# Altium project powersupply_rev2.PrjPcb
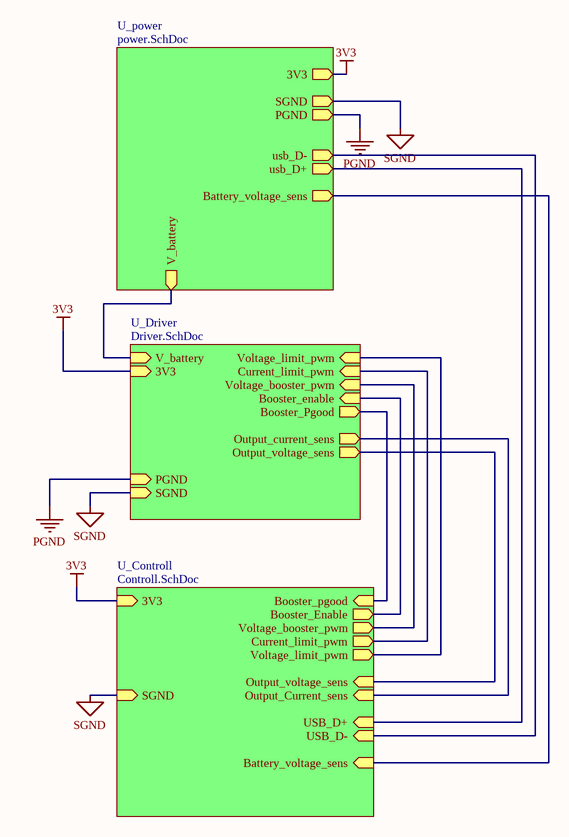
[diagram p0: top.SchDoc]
16 sheets, 127 parts. Net scope: strictly hierarchical (ports join the sheet entries above them; power ports are local).
Board file: PCB1.PcbDoc
Sheets:
  top.SchDoc
    U_power = power.SchDoc
      LDO = LDO.SchDoc
      Battery = battery.SchDoc
      U_usb = usb.SchDoc
      U_usb_isolator = usb_isolator.SchDoc
    U_Driver = Driver.SchDoc
      U_Booster = Booster.SchDoc
      pta_I = pwm_to_analog.SchDoc
      U_current_sense = current_sense.SchDoc
      U_linear_regulator = linear_regulator.SchDoc
      pta_I = pwm_to_analog.SchDoc
      pta_I = pwm_to_analog.SchDoc
    U_Controll = Controll.SchDoc
      U_knobs = knobs.SchDoc
      U_mcu = mcu.SchDoc
      U_Display = Display.SchDoc
      U_programmer = programmer.SchDoc

## Sheet top.SchDoc
size A3

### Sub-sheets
U_Controll = Controll.SchDoc: 3V3 (in), SGND (in), Booster_pgood (in), Booster_Enable (out), Voltage_limit_pwm (out), Current_limit_pwm (out), USB_D+ (in), USB_D- (in), Battery_voltage_sens (in), Voltage_booster_pwm (out), Output_voltage_sens (in), Output_Current_sens (in)
U_Driver = Driver.SchDoc: V_battery (in), SGND (in), PGND (in), 3V3 (in), Voltage_limit_pwm (in), Current_limit_pwm (in), Booster_enable (in), Booster_Pgood (out), Voltage_booster_pwm (in), Output_current_sens (out), Output_voltage_sens (out)
U_power = power.SchDoc: usb_D- (out), usb_D+ (out), 3V3 (out), SGND (out), PGND (out), V_battery (out), Battery_voltage_sens (out)

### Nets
3V3: sheet U_power/3V3, sheet U_Driver/3V3, sheet U_Controll/3V3
PGND: sheet U_power/PGND, sheet U_Driver/PGND
SGND: sheet U_power/SGND, sheet U_Driver/SGND, sheet U_Controll/SGND  [project net GND]
Net*2_3: sheet U_Driver/Output_current_sens, sheet U_Controll/Output_Current_sens
NetC17_1: sheet U_power/V_battery, sheet U_power/Battery_voltage_sens, sheet U_Driver/V_battery, sheet U_Controll/Battery_voltage_sens
NetIC1_1: sheet U_Driver/Booster_enable, sheet U_Controll/Booster_Enable
NetIC1_17: sheet U_Driver/Booster_Pgood, sheet U_Controll/Booster_pgood
NetR20_pta_I1_1: sheet U_Driver/Current_limit_pwm, sheet U_Controll/Current_limit_pwm
NetR20_pta_I2_1: sheet U_Driver/Voltage_limit_pwm, sheet U_Controll/Voltage_limit_pwm
NetR20_pta_I3_1: sheet U_Driver/Voltage_booster_pwm, sheet U_Controll/Voltage_booster_pwm
NetR24_2: sheet U_power/usb_D+, sheet U_Controll/USB_D+
NetR26_2: sheet U_power/usb_D-, sheet U_Controll/USB_D-
NetR29_1: sheet U_Driver/Output_voltage_sens, sheet U_Controll/Output_voltage_sens

## Sheet power.SchDoc
size A3
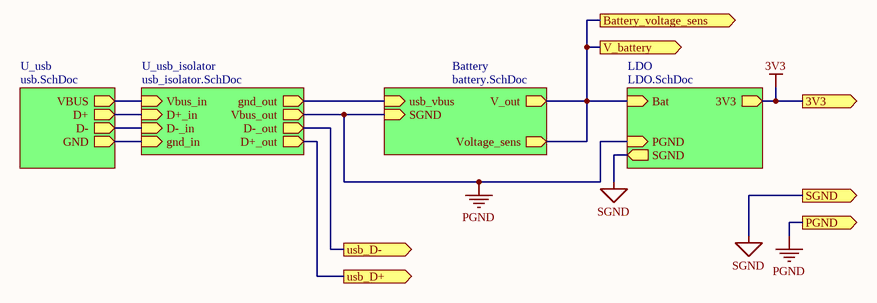
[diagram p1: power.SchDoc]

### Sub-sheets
Battery = battery.SchDoc: V_out (out), Voltage_sens (out), usb_vbus (in), SGND (in)
LDO = LDO.SchDoc: Bat (in), PGND (in), 3V3 (out), SGND (out)
U_usb = usb.SchDoc: VBUS (out), GND (out), D+ (out), D- (out)
U_usb_isolator = usb_isolator.SchDoc: Vbus_in (in), D+_in (in), D-_in (in), gnd_in (in), gnd_out (out), D-_out (out), D+_out (out), Vbus_out (out)

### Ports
3V3 (out), Battery_voltage_sens (out), PGND (out), SGND (out), usb_D+ (out), usb_D- (out), V_battery (out)

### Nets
3V3: port 3V3, sheet LDO/3V3
PGND: port PGND, sheet LDO/PGND, sheet Battery/SGND, sheet U_usb_isolator/Vbus_out
SGND: port SGND, sheet LDO/SGND  [project net GND]
NetC13_2: sheet Battery/usb_vbus, sheet U_usb_isolator/gnd_out
NetC17_1: port V_battery, port Battery_voltage_sens, sheet LDO/Bat, sheet Battery/V_out, sheet Battery/Voltage_sens
NetC42_1: sheet U_usb/GND, sheet U_usb_isolator/gnd_in
NetC42_2: sheet U_usb/VBUS, sheet U_usb_isolator/Vbus_in
NetJ1_A6: sheet U_usb/D+, sheet U_usb_isolator/D+_in
NetJ1_A7: sheet U_usb/D-, sheet U_usb_isolator/D-_in
NetR24_2: port usb_D+, sheet U_usb_isolator/D+_out
NetR26_2: port usb_D-, sheet U_usb_isolator/D-_out

## Sheet LDO.SchDoc
size A4
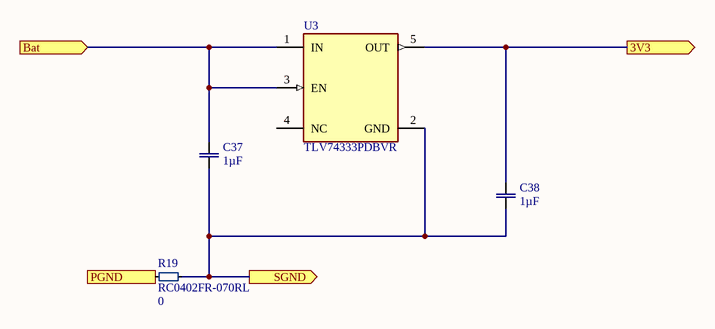
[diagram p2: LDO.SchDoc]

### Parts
C37  Capacitance: 1µF  [CAP0805]  (hidden comment: CL21B105KBFNNNG)
C38  Capacitance: 1µF  [CAP0805]  (hidden comment: CL21B105KBFNNNG)
R19  RC0402FR-070RL  Resistance: 0  [SMD_0402(1005)_M]
U3  TLV74333PDBVR  [FP-DBV0005A-IPC_A]

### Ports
3V3 (out), Bat (in), PGND (in), SGND (out)

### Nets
3V3: C38.2 U3.5(OUT) ; port 3V3
GND: C37.1 C38.1 R19.2 U3.2(GND) ; port SGND
PGND: R19.1 ; port PGND
NetC17_1: C37.2 U3.1(IN) U3.3(EN) ; port Bat

Not connected (* = marked no-connect by the designer): U3 4(NC)

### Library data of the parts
C37 C38 = CMP-0001-00012-4: SAMSUNG ELECTRO-MECHANICS - CL21B105KBFNNNG - MLCC CAPACITORS; Voltage Rating: 50V; Dielectric: X7R; Material: Ceramic; Tolerance: 10%
R19 = CMP-0001-00005-6: Res Thick Film 0402 0 Ohm Molded SMD SMD Paper T/R; Value: 0; Temperature Coefficient: 200ppm/°C; Power Rating: 62.5mW; Voltage Rating: 50V; Tolerance: 1%
U3 = CMP-00004-1: 300mA Low-Dropout (LDO) Regulator 5-SOT-23 -40 to 125; Power Supply Rejection Ratio (PSRR): 28dB; Dropout Voltage: 270mV; Min Output Voltage: 3.3V; Output Configuration: Positive; Max Input Voltage: 5.5V; Output Type: Fixed; Number of Regulators: 1; Quiescent Current: 60uA

## Sheet battery.SchDoc
size A4
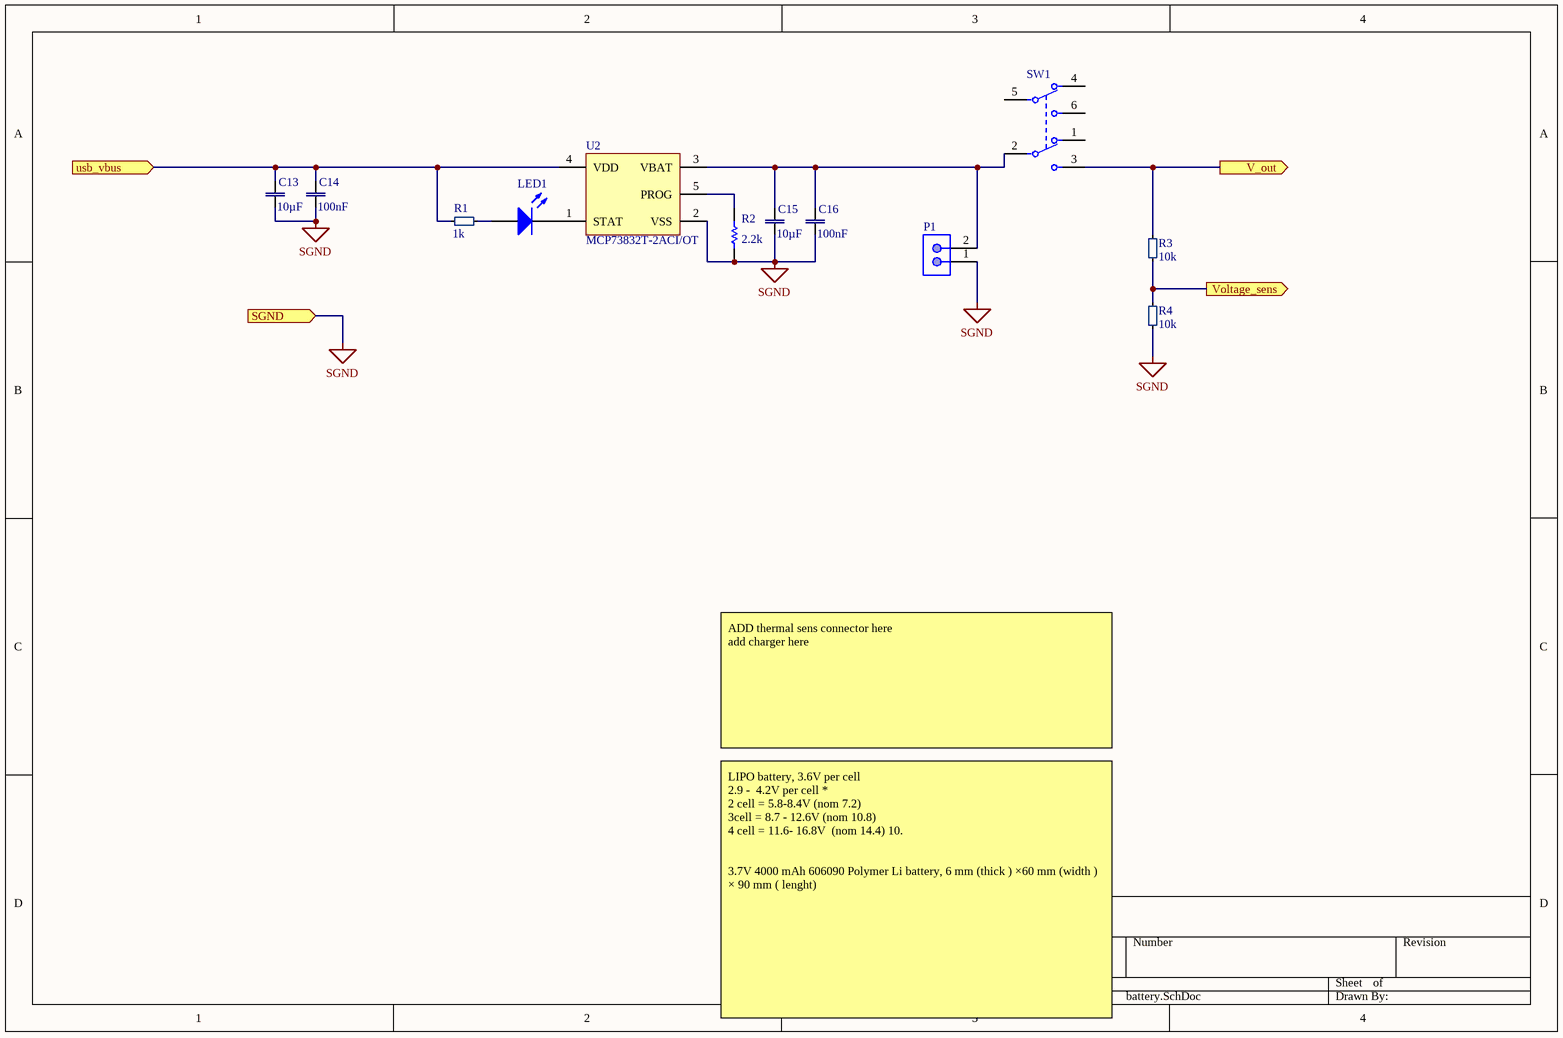
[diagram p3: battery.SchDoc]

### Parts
C13  Capacitance: 10µF  [Chip2PinSM127P600-8N]  (hidden comment: CL31A106MBHNNNE)
C14  Capacitance: 100nF  [cap0402]  (hidden comment: GRM155R71H104ME14D)
C15  Capacitance: 10µF  [Chip2PinSM127P600-8N]  (hidden comment: CL31A106MBHNNNE)
C16  Capacitance: 100nF  [cap0402]  (hidden comment: GRM155R71H104ME14D)
LED1  150080BS75000  [0805_A]  (value not drawn)
P1  B2B-XH-A(LF)(SN)  [JST-B2B-XH-A_V]  (value not drawn)
R1  Resistance: 1k  [SMD_0402(1005)_M]  (hidden comment: RC0402FR-071KL)
R2  Resistance: 2.2k  [RESC1005X40X25NL05T10]  (hidden comment: RC0402FR-072K2L)
R3  Resistance: 10k  [SMD_0402(1005)_M]  (hidden comment: RC0402FR-0710KL)
R4  Resistance: 10k  [SMD_0402(1005)_M]  (hidden comment: RC0402FR-0710KL)
SW1  100DP1T2B3M2QEH  [FP-100DP1T2B3M2QEH-MFG]  (value not drawn)
U2  MCP73832T-2ACI/OT  [SOT-23-OT5_M]

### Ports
SGND (in), usb_vbus (in), V_out (out), Voltage_sens (out)

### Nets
SGND: C13.1 C14.1 C15.1 C16.1 P1.1 R2.1 R4.1 U2.2(VSS) ; port SGND  [project net PGND]
NetC13_2: C13.2 C14.2 R1.2 U2.4(VDD) ; port usb_vbus
NetC15_2: C15.2 C16.2 P1.2 SW1.2 U2.3(VBAT)
NetC17_1: R3.1 R3.2 R4.2 SW1.3 ; port V_out, port Voltage_sens
NetLED1_1: LED1.1(K) U2.1(STAT)
NetLED1_2: LED1.2(A) R1.1
NetR2_2: R2.2 U2.5(PROG)

Not connected (* = marked no-connect by the designer): SW1 1 4 5 6

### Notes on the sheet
- ADD thermal sens connector here
  add charger here
- LIPO battery, 3.6V per cell
  2.9 -  4.2V per cell *
  2 cell = 5.8-8.4V (nom 7.2)
  3cell = 8.7 - 12.6V (nom 10.8)
  4 cell = 11.6- 16.8V  (nom 14.4) 10.
  3.7V 4000 mAh 606090 Polymer Li battery, 6 mm (thick ) ×60 mm (width ) × 90 mm ( lenght)

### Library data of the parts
C13 C15 = CMP-0001-00015-2: CAP CER 10UF 50V X5R 1206; Capacitor Type: Ceramic; Tolerance: 20%
C14 C16 = CMP-0001-00001-8: 0402 0.1 uF 50 V ±20% Tolerance X7R SMT Monolithic Ceramic Chip Capacitor; Value: 100nF; Voltage Rating: 50V
LED1 = CMP-00002-1: SMD LED blue 3.5 V 0805, 150080BS75000, Würth Elektronik; Dominant Wavelength: 470nm; Luminous Intensity: 145mcd; Lens Style: Clear,Rectangular; Forward Current: 30mA; Test Current: 20mA; Forward Voltage: 3.2V; Viewing Angle: 140°
P1 = CMP-ROOT-00008-1: Conn Shrouded Header (4 Sides) HDR 2 POS 2.5mm Solder ST Thru-Hole Box; Max Current Rating: 3A; Connector Type: Male Pin; Contact Resistance: 20mR; Max Voltage Rating (DC): 250V; System: Connector; Wire/Cable Gauge: 22AWG; Number of Contacts: 2; Insulation Resistance: 1GR
R1 = CMP-001-0000-7: Surface Mount Chip Resistor, Thick Film, RC Series, 1 kohm, 62.5 mW, 1%, 50 V, 0402 [1005 Metric]; Temperature Coefficient: 100ppm/°C; Value: 1k; Voltage Rating: 50V; Power Rating: 62.5mW
R2 = CMP-001-0020-3: RES SMD 2.2K OHM 1% 1/16W 0402; Temperature Coefficient: 100ppm/°C; Voltage Rating: 50V; Power Rating: 63mW
R3 R4 = CMP-008-0005-9: Surface Mount Thick Film Resistor, Rc Series, 10 Kohm, 62.5 Mw, - 1%, 50 V, 0402 [1005 Metric]; Voltage Rating (DC): 50V; Value: 10k; Temperature Coefficient: 100ppm/°C; Power Rating: 62.5mW
SW1 = CMP-ROOT-00014-1: 100 Series DPDT On-None-On Through Hole Miniature Toggle Switch; Illumination Type: Non-Illuminated; Actuator Type: Standard Round; Switch Function: On-On; Actuator Length: 6.86mm; Voltage Rating (AC): 120V; Actuator Material: Brass,Chrome; Current Rating: 5A; Voltage Rating (DC): 28V; Electrical Life: 40000Cycles
U2 = CMP-006-0003-2: BATTERY CHARGER, 500mA, SOT23-5; Battery Type:Li-Ion, Li-Pol; Input Voltage:6V; Battery Charge Voltage:4.2V; Charge Current Max:500mA; Battery IC Case Style:SOT-23; No. of Pins:5; No. of Series Cells:1; Operating Temperature Max:85 C; Max Supply Voltage: 6V; Number of Cells: 1; Max Output Voltage: 4.5V; Max Power Dissipation: 1.54W; Min Supply Voltage: 3.75V; Min Output Voltage: 4.168V; Output Current: 10mA; Output Voltage: 4.2V

## Sheet usb.SchDoc
size A3
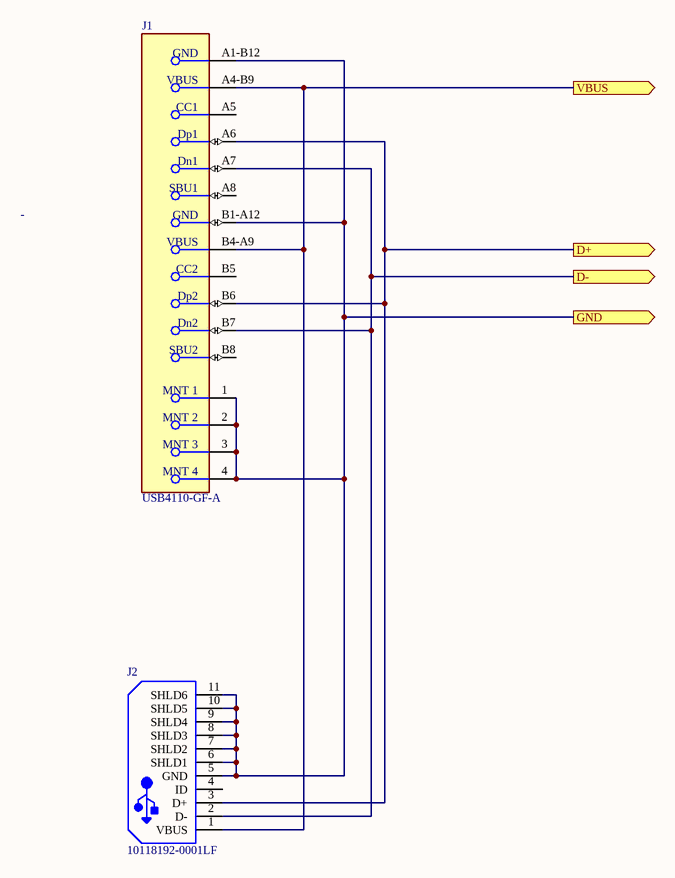
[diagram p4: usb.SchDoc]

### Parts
J1  USB4110-GF-A  [FP-USB4110-GF-A-MFG]
J2  10118192-0001LF  [FCI-10118192-0001LF-5_V]

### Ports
D+ (out), D- (out), GND (out), VBUS (out)

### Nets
NetC42_1: J1.1(MNT_1) J1.2(MNT_2) J1.3(MNT_3) J1.4(MNT_4) J1.A1-B12(GND) J1.B1-A12(GND) J2.5(GND) J2.6(SHLD1) J2.7(SHLD2) J2.8(SHLD3) J2.9(SHLD4) J2.10(SHLD5) J2.11(SHLD6) ; port GND
NetC42_2: J1.A4-B9(VBUS) J1.B4-A9(VBUS) J2.1(VBUS) ; port VBUS
NetJ1_A6: J1.A6(Dp1) J1.B6(Dp2) J2.3(D+) ; port D+
NetJ1_A7: J1.A7(Dn1) J1.B7(Dn2) J2.2(D-) ; port D-

Not connected (* = marked no-connect by the designer): J1 A5(CC1) A8(SBU1) B5(CC2) B8(SBU2); J2 4(ID)

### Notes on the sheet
- -

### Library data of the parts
J1 = CMP-ROOT-00018-1: Conn Usb 2.0 Type-c R/a SMT; Number of Positions: 12; System: Connector
J2 = CMP-ROOT-00010-2: CONN RCPT USB2.0 MICRO B SMD R/A; Voltage Rating: 100V; Number of Contacts: 5; Gender: Receptacle; System: Connector; Connector Type: USB,Receptacle; Current Rating: 1.8A; Number of Ports: 1; Insulation Resistance: 1GR; Pitch: 0.65mm

## Sheet usb_isolator.SchDoc
size A3
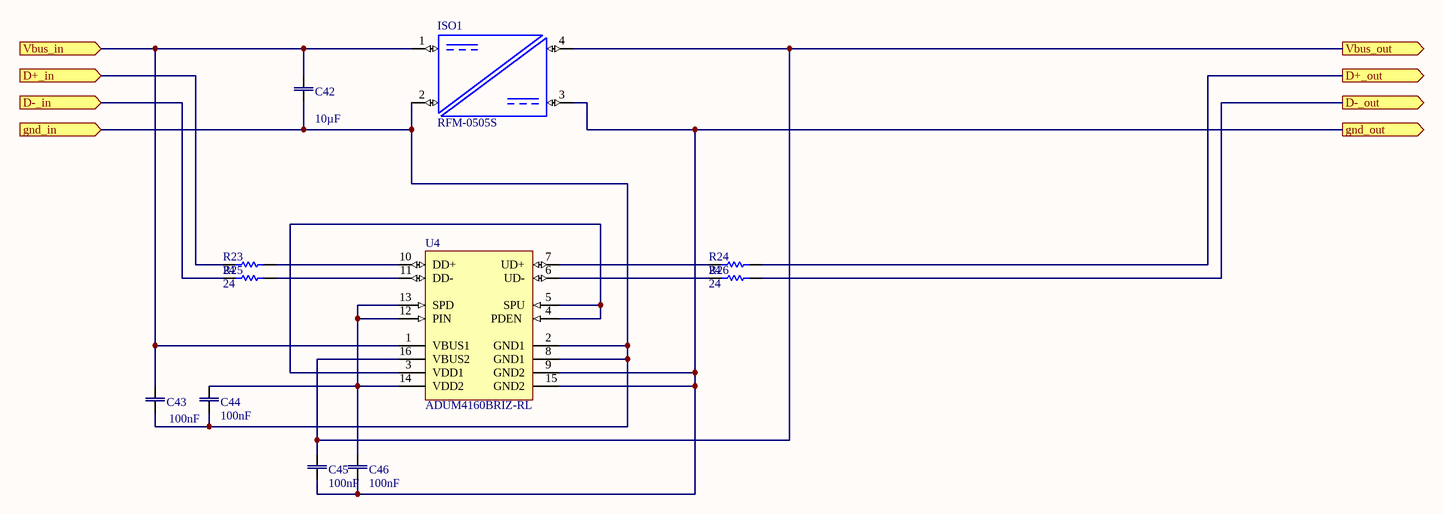
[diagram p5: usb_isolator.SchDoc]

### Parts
C42  Capacitance: 10µF  [Chip2PinSM127P600-8N]  (hidden comment: CL31A106MBHNNNE)
C43  Capacitance: 100nF  [cap0402]  (hidden comment: GRM155R71H104ME14D)
C44  Capacitance: 100nF  [cap0402]  (hidden comment: GRM155R71H104ME14D)
C45  Capacitance: 100nF  [cap0402]  (hidden comment: GRM155R71H104ME14D)
C46  Capacitance: 100nF  [cap0402]  (hidden comment: GRM155R71H104ME14D)
ISO1  RFM-0505S  [RFM-0505S-Footprint-1]
R23  Resistance: 24  [RESC1005X40X25ML05T10]  (hidden comment: RC0402FR-0724RL)
R24  Resistance: 24  [RESC1005X40X25ML05T10]  (hidden comment: RC0402FR-0724RL)
R25  Resistance: 24  [RESC1005X40X25ML05T10]  (hidden comment: RC0402FR-0724RL)
R26  Resistance: 24  [RESC1005X40X25ML05T10]  (hidden comment: RC0402FR-0724RL)
U4  ADUM4160BRIZ-RL  [ADI-RI-16-1_M]

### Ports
D+_in (in), D+_out (out), D-_in (in), D-_out (out), gnd_in (in), gnd_out (out), Vbus_in (in), Vbus_out (out)

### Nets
PGND: C45.1 ISO1.4(+Vout) U4.16(VBUS2) ; port Vbus_out
NetC13_2: C45.2 C46.2 ISO1.3(-Vout) U4.9(GND2) U4.15(GND2) ; port gnd_out
NetC42_1: C42.1 C43.1 C44.2 ISO1.2(+Vin) U4.2(GND1) U4.8(GND1) ; port gnd_in
NetC42_2: C42.2 C43.2 ISO1.1(-Vin) U4.1(VBUS1) ; port Vbus_in
NetC44_1: C44.1 C46.1 U4.12(PIN) U4.13(SPD) U4.14(VDD2)
NetJ1_A6: R23.1 ; port D+_in
NetJ1_A7: R25.1 ; port D-_in
NetR23_2: R23.2 U4.10(DD+)
NetR24_1: R24.1 U4.7(UD+)
NetR24_2: R24.2 ; port D+_out
NetR25_2: R25.2 U4.11(DD-)
NetR26_1: R26.1 U4.6(UD-)
NetR26_2: R26.2 ; port D-_out
NetU4_3: U4.3(VDD1) U4.4(PDEN) U4.5(SPU)

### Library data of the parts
C42 = CMP-0001-00015-2: as C13 on sheet battery
C43-C46 = CMP-0001-00001-8: as C14 on sheet battery
ISO1 = CMP-ROOT-00011-2: RECOM POWER - RFM-0505S - Isolated Board Mount DC/DC Converter, ITE & General, 1 Output, 1 W, 5 V, 200 mA; Max Output Voltage: 5V
R23-R26 = CMP-0001-00017-2: Thick Film Resistors 24 OHM 1%; Voltage Rating: 50V; Temperature Coefficient: 100ppm/°C; Power Rating: 63mW
U4 = CMP-00003-1: Digital Isolator CMOS 4-CH 12Mbps 16-Pin SOIC T/R; Turn-On Delay Time: 60ns; Channel Type: Bidirectional; Isolated Power: No; Min Supply Voltage: 3.1V; Max Supply Voltage: 5.5V; Nominal Supply Current: 6mA; Propagation Delay: 70ns; Number of Channels: 2

## Sheet Driver.SchDoc
size A3
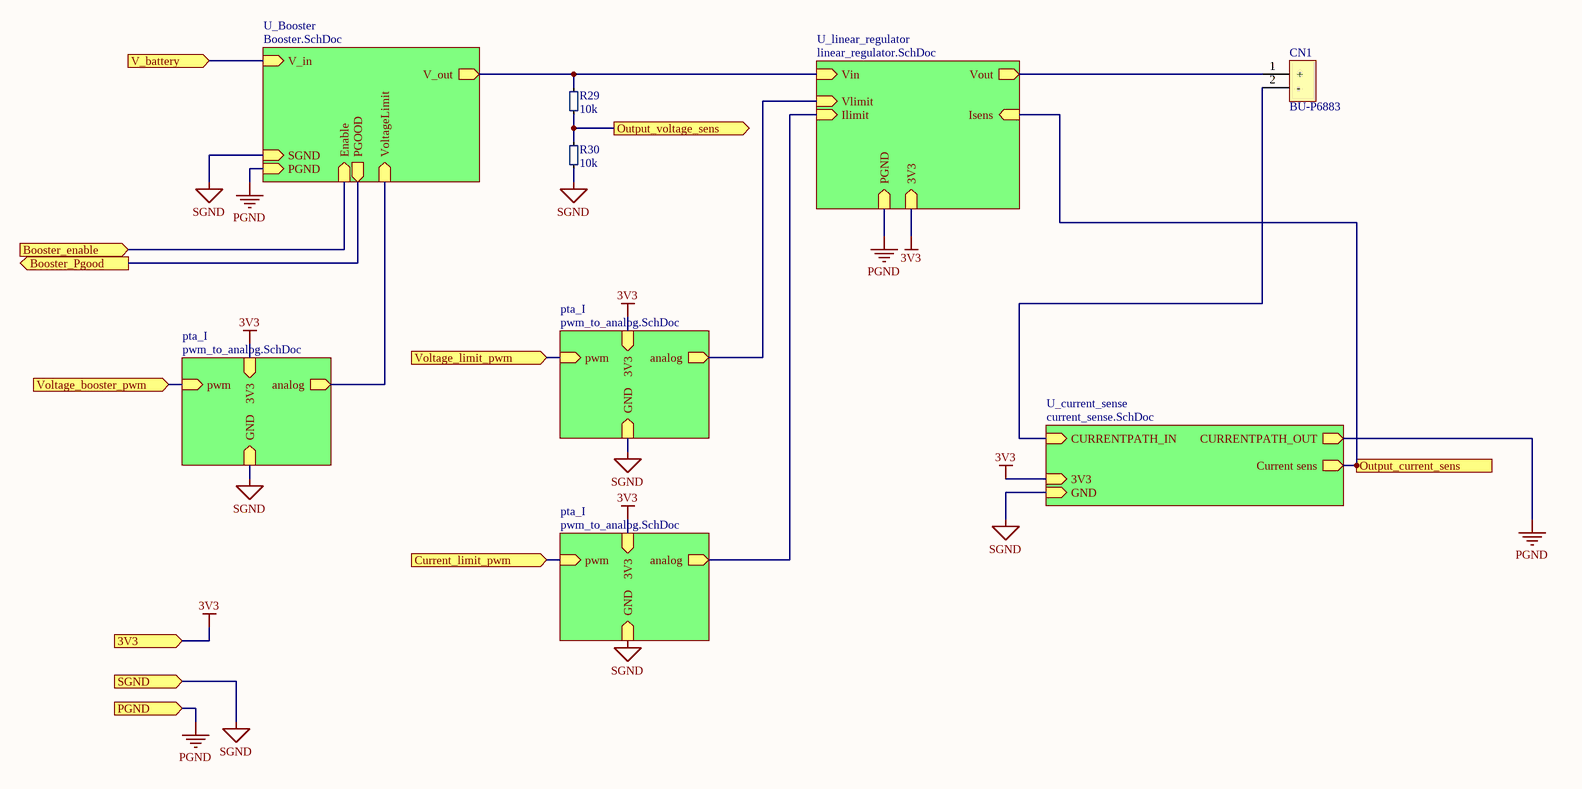
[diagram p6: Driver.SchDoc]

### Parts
CN1  BU-P6883  [6883-Footprint-1]
R29  Resistance: 10k  [SMD_0402(1005)_M]  (hidden comment: RC0402FR-0710KL)
R30  Resistance: 10k  [SMD_0402(1005)_M]  (hidden comment: RC0402FR-0710KL)

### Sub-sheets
pta_I = pwm_to_analog.SchDoc: pwm (in), analog (out), GND (in), 3V3 (in)
pta_I = pwm_to_analog.SchDoc: pwm (in), analog (out), GND (in), 3V3 (in)
pta_I = pwm_to_analog.SchDoc: pwm (in), analog (out), GND (in), 3V3 (in)
U_Booster = Booster.SchDoc: VoltageLimit (in), V_in (in), Enable (in), V_out (out), PGOOD (out), SGND (in), PGND (in)
U_current_sense = current_sense.SchDoc: CURRENTPATH_IN (in), CURRENTPATH_OUT (out), GND (in), 3V3 (in), Current sens (out)
U_linear_regulator = linear_regulator.SchDoc: 3V3 (in), PGND (in), Vlimit (in), Ilimit (in), Vin (in), Isens (in), Vout (out)

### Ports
3V3 (in), Booster_enable (in), Booster_Pgood (out), Current_limit_pwm (in), Output_current_sens (out), Output_voltage_sens (out), PGND (in), SGND (in), V_battery (in), Voltage_booster_pwm (in), Voltage_limit_pwm (in)

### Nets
3V3: port 3V3, sheet pta_I/3V3, sheet U_current_sense/3V3, sheet U_linear_regulator/3V3, sheet pta_I/3V3, sheet pta_I/3V3
PGND: port PGND, sheet U_Booster/PGND, sheet U_current_sense/CURRENTPATH_OUT, sheet U_linear_regulator/PGND
SGND: R30.1 ; port SGND, sheet U_Booster/SGND, sheet pta_I/GND, sheet U_current_sense/GND, sheet pta_I/GND, sheet pta_I/GND  [project net GND]
Net*1_pta_I1_3: sheet U_linear_regulator/Ilimit, sheet pta_I/analog
Net*1_pta_I2_3: sheet U_linear_regulator/Vlimit, sheet pta_I/analog
Net*1_pta_I3_3: sheet U_Booster/VoltageLimit, sheet pta_I/analog
Net*2_3: port Output_current_sens, sheet U_current_sense/Current sens, sheet U_linear_regulator/Isens
NetC17_1: port V_battery, sheet U_Booster/V_in
NetC18_1: R29.2 ; sheet U_Booster/V_out, sheet U_linear_regulator/Vin
NetC48_2: CN1.1(+) ; sheet U_linear_regulator/Vout
NetCN1_2: CN1.2(-) ; sheet U_current_sense/CURRENTPATH_IN
NetIC1_1: port Booster_enable, sheet U_Booster/Enable
NetIC1_17: port Booster_Pgood, sheet U_Booster/PGOOD
NetR20_pta_I1_1: port Current_limit_pwm, sheet pta_I/pwm
NetR20_pta_I2_1: port Voltage_limit_pwm, sheet pta_I/pwm
NetR20_pta_I3_1: port Voltage_booster_pwm, sheet pta_I/pwm
NetR29_1: R29.1 R30.2 ; port Output_voltage_sens

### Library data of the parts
CN1 = CMP-ROOT-00006-6: CONN BIND POST DL FLUTD BLK/RED; Number of Positions: 2; System: Connector
R29 R30 = CMP-008-0005-9: Surface Mount Thick Film Resistor, Rc Series, 10 Kohm, 62.5 Mw, - 1%, 50 V, 0402 [1005 Metric]; Voltage Rating: 50V; Power Rating: 62.5mW; Value: 10k; Temperature Coefficient: 100ppm/°C

## Sheet Booster.SchDoc
size A3
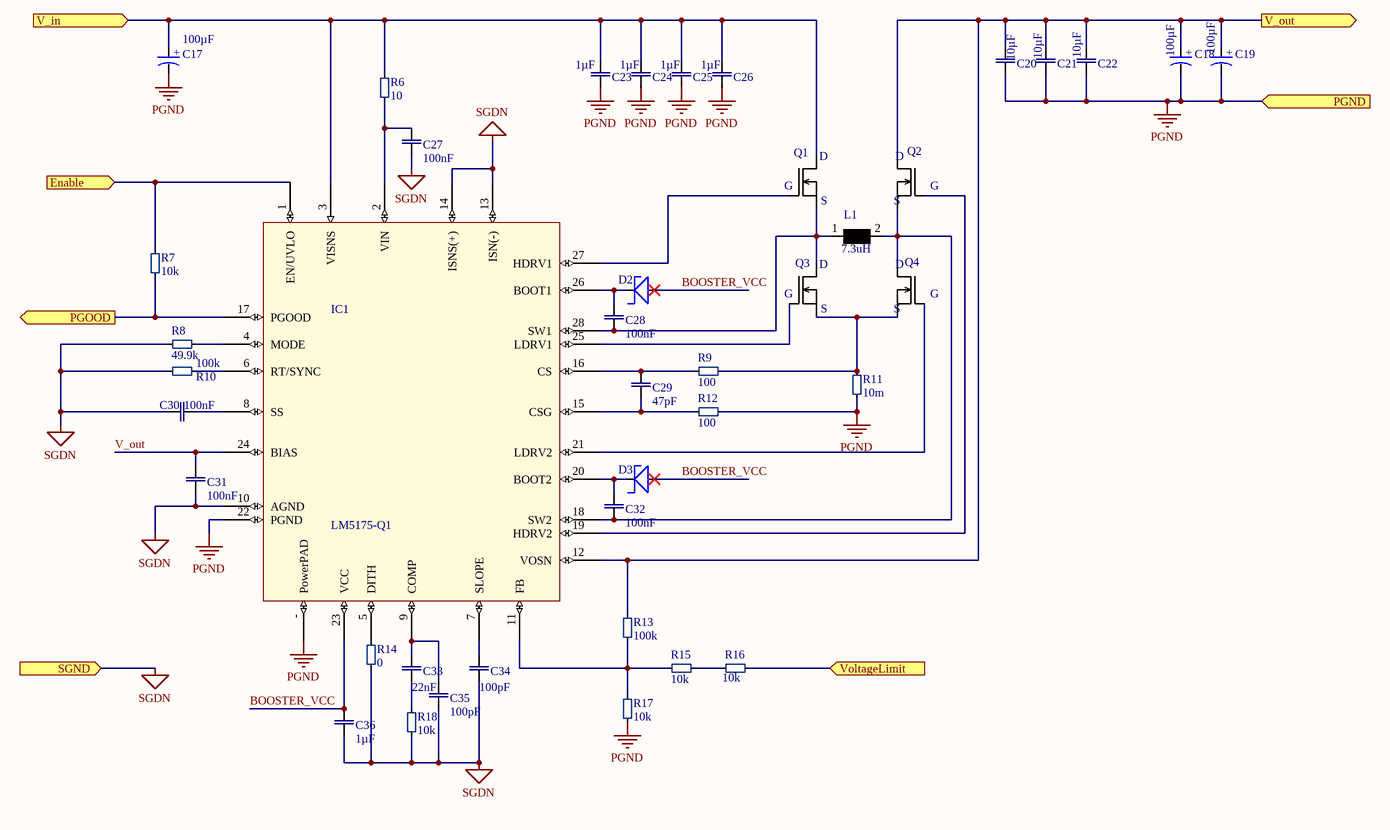
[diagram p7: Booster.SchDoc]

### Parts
C17  Capacitance: 100µF  [CAPAE9983X102N]  (hidden comment: EEE-1HA101UP)
C18  Capacitance: 100µF  [CAPAE9983X102N]  (hidden comment: EEE-1HA101UP)
C19  Capacitance: 100µF  [CAPAE9983X102N]  (hidden comment: EEE-1HA101UP)
C20  Capacitance: 10µF  [Chip2PinSM127P600-8N]  (hidden comment: CL31A106MBHNNNE)
C21  Capacitance: 10µF  [Chip2PinSM127P600-8N]  (hidden comment: CL31A106MBHNNNE)
C22  Capacitance: 10µF  [Chip2PinSM127P600-8N]  (hidden comment: CL31A106MBHNNNE)
C23  Capacitance: 1µF  [CAP0805]  (hidden comment: CL21B105KBFNNNG)
C24  Capacitance: 1µF  [CAP0805]  (hidden comment: CL21B105KBFNNNG)
C25  Capacitance: 1µF  [CAP0805]  (hidden comment: CL21B105KBFNNNG)
C26  Capacitance: 1µF  [CAP0805]  (hidden comment: CL21B105KBFNNNG)
C27  value 100nF  [cap0402]  (hidden comment: GRM155R71H104ME14D)
C28  value 100nF  [cap0402]  (hidden comment: GRM155R71H104ME14D)
C29  Capacitance: 47pF  [cap0402]  (hidden comment: 885012005078)
C30  value 100nF  [cap0402]  (hidden comment: GRM155R71H104ME14D)
C31  value 100nF  [cap0402]  (hidden comment: GRM155R71H104ME14D)
C32  value 100nF  [cap0402]  (hidden comment: GRM155R71H104ME14D)
C33  Capacitance: 22nF  [cap0402]  (hidden comment: CC0402KRX7R9BB223)
C34  Capacitance: 100pF  [cap0402]  (hidden comment: 885012005080)
C35  Capacitance: 100pF  [cap0402]  (hidden comment: 885012005080)
C36  Capacitance: 1µF  [CAP0805]  (hidden comment: CL21B105KBFNNNG)
D2  PMEG60T10ELPX  [SODFL470X110-2N]  (value not drawn)
D3  PMEG60T10ELPX  [SODFL470X110-2N]  (value not drawn)
IC1  LM5175-Q1  [HTSSOP-28]
L1  Inductance: 7.3uH  [INDP130128X65N]  (hidden comment: 7443551730)
Q1  PMN55ENEX  [TSOP95P280X110-6N_PMN55ENE]  (value not drawn)
Q2  PMN55ENEX  [TSOP95P280X110-6N_PMN55ENE]  (value not drawn)
Q3  PMN55ENEX  [TSOP95P280X110-6N_PMN55ENE]  (value not drawn)
Q4  PMN55ENEX  [TSOP95P280X110-6N_PMN55ENE]  (value not drawn)
R6  Resistance: 10  [SMD_0402(1005)_M]  (hidden comment: RC0402FR-0710RL)
R7  Resistance: 10k  [SMD_0402(1005)_M]  (hidden comment: RC0402FR-0710KL)
R8  Resistance: 49.9k  [SMD_0402(1005)_M]  (hidden comment: RC0402FR-0749K9L)
R9  Resistance: 100  [SMD_0402(1005)_M]  (hidden comment: RC0402FR-07100RL)
R10  Resistance: 100k  [SMD_0402(1005)_M]  (hidden comment: RC0402FR-07100KL)
R11  Resistance: 10m  [Chip2PinSM127P600-8N]  (hidden comment: CFG0612-FX-R010ELF)
R12  Resistance: 100  [SMD_0402(1005)_M]  (hidden comment: RC0402FR-07100RL)
R13  Resistance: 100k  [SMD_0402(1005)_M]  (hidden comment: RC0402FR-07100KL)
R14  Resistance: 0  [SMD_0402(1005)_M]  (hidden comment: RC0402FR-070RL)
R15  Resistance: 10k  [SMD_0402(1005)_M]  (hidden comment: RC0402FR-0710KL)
R16  Resistance: 10k  [SMD_0402(1005)_M]  (hidden comment: RC0402FR-0710KL)
R17  Resistance: 10k  [SMD_0402(1005)_M]  (hidden comment: RC0402FR-0710KL)
R18  Resistance: 10k  [SMD_0402(1005)_M]  (hidden comment: RC0402FR-0710KL)

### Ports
Enable (in), PGND (in), PGOOD (out), SGND (in), V_in (in), V_out (out), VoltageLimit (in)

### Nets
PGND: C17.2(-) C18.2(-) C19.2(-) C20.1 C21.1 C22.1 C23.1 C24.1 C25.1 C26.1 IC1.22(PGND) IC1.-(PowerPAD) R11.1 R12.2 R17.1 ; port PGND
SGDN: C27.2 C30.1 C31.1 C34.1 C35.1 C36.2 IC1.10(AGND) IC1.13(ISN(-)) IC1.14(ISNS(+)) R8.1 R10.1 R14.1 R18.1 ; port SGND  [project net GND]
BOOSTER_VCC: C36.1 D2.2(A) D3.2(A) IC1.23(VCC)
V_out: C31.2 IC1.24(BIAS)
Net*1_pta_I3_3: R16.2 ; port VoltageLimit
NetC17_1: C17.1(+) C23.2 C24.2 C25.2 C26.2 IC1.3(VISNS) Q1.2(S) R6.2 ; port V_in
NetC18_1: C18.1(+) C19.1(+) C20.2 C21.2 C22.2 IC1.12(VOSN) Q2.2(S) R13.2 ; port V_out
NetC27_1: C27.1 IC1.2(VIN) R6.1
NetC28_1: C28.1 IC1.28(SW1) L1.1 Q1.1(D) Q3.2(S)
NetC28_2: C28.2 D2.1(K) IC1.26(BOOT1)
NetC29_1: C29.1 IC1.16(CS) R9.1
NetC29_2: C29.2 IC1.15(CSG) R12.1
NetC30_2: C30.2 IC1.8(SS)
NetC32_1: C32.1 IC1.18(SW2) L1.2 Q2.1(D) Q4.2(S)
NetC32_2: C32.2 D3.1(K) IC1.20(BOOT2)
NetC33_1: C33.1 R18.2
NetC33_2: C33.2 C35.2 IC1.9(COMP)
NetC34_2: C34.2 IC1.7(SLOPE)
NetIC1_1: IC1.1(EN/UVLO) R7.2 ; port Enable
NetIC1_4: IC1.4(MODE) R8.2
NetIC1_5: IC1.5(DITH) R14.2
NetIC1_6: IC1.6(RT/SYNC) R10.2
NetIC1_11: IC1.11(FB) R13.1 R15.1 R17.2
NetIC1_17: IC1.17(PGOOD) R7.1 ; port PGOOD
NetIC1_19: IC1.19(HDRV2) Q2.3(G)
NetIC1_21: IC1.21(LDRV2) Q4.3(G)
NetIC1_25: IC1.25(LDRV1) Q3.3(G)
NetIC1_27: IC1.27(HDRV1) Q1.3(G)
NetQ3_1: Q3.1(D) Q4.1(D) R9.2 R11.2
NetR15_2: R15.2 R16.1

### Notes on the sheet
- 100k = 250kHz

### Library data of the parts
C17-C19 = CMP-0001-00014-2: Cap Aluminum 100uF 50V 20% (8 X 10.2mm) SMD 200mA 2000 hr 85C T/R; Capacitor Type: Ceramic; Life (Hours): 2000Hour
C20-C22 = CMP-0001-00015-2: as C13 on sheet battery
C23-C26 = CMP-0001-00012-4: as C37 on sheet LDO
C27 C28 C30-C32 = CMP-0001-00001-8: 0402 0.1 uF 50 V ±20% Tolerance X7R SMT Monolithic Ceramic Chip Capacitor; Voltage Rating: 50V
C29 = CMP-0001-00009-6: CAP CER 47PF 100V C0G/NP0 0402; Tolerance: 5%; Capacitor Type: Ceramic
C33 = CMP-0001-00011-3: Multilayer Ceramic Capacitors MLCC - SMD/SMT 22K pF 10% 50 Volts; Dielectric: X7R; Voltage Rating (DC): 50V
C34 C35 = CMP-0001-00010-3: Cap, Mlcc, C0g, 100Pf, 100V, 0402; Capacitor Type: Ceramic; Tolerance: 5%
C36 = CMP-0001-00012-4: SAMSUNG ELECTRO-MECHANICS - CL21B105KBFNNNG - MLCC CAPACITORS; Dielectric: X7R; Tolerance: 10%; Material: Ceramic; Voltage Rating: 50V
D2 D3 = CMP-ROOT-00002-1: Diode Schottky 60V 1A Surface Mount CFP5; Voltage - Forward (Vf) (Max) @ If: 590mV @ 1A
IC1 = CMP-006-0002-14: IC REG CTRLR BUCK-BOOST 28HTSSOP; Switching Frequency: 600kHz; Number of Outputs: 2; Synchronous Rectifier: Yes; Number of Output Phases: 1; Quiescent Current: 1.65mA; Min Supply Voltage: 3.5V; Max Supply Voltage: 42V; Output Configuration: Positive
L1 = CMP-ROOT-00003-1: WURTH ELEKTRONIK         7443551730             Surface Mount Power Inductor, WE-HCI Series, 7.3 H, 13 A, 12 A, Shielded, 5900 ohm; Tolerance: 20%; Max DC Current: 13A; DC Resistance (DCR): 5.9mR; Saturation Current: 12A; Series Resistance: 5.9R; Test Frequency: 100kHz; Self Resonant Frequency: 28MHz
Q1 = CMP-ROOT-00001-4: MOSFET N-CH 60V 4.5A 6TSOP; Input Capacitance: 646pF; Max Power Dissipation: 6.25mW; Rds On Max: 60mR
Q2-Q4 = CMP-ROOT-00001-4: MOSFET N-CH 60V 4.5A 6TSOP; Input Capacitance: 646pF; Rds On Max: 60mR; Max Power Dissipation: 6.25mW
R6 = CMP-0001-00007-3: RES SMD 10 OHM 1% 1/16W 0402; Working Voltage: 50V; Value: 10; Power Rating: 63mW; Temperature Coefficient: 100ppm/°C
R7 = CMP-008-0005-9: Surface Mount Thick Film Resistor, Rc Series, 10 Kohm, 62.5 Mw, - 1%, 50 V, 0402 [1005 Metric]; Voltage Rating: 50V; Temperature Coefficient: 100ppm/°C; Power Rating: 62.5mW; Value: 10k
R8 = CMP-0001-00013-2: Res Thick Film 0402 49.9K Ohm 1% 0.063W(1/16W) ±100ppm/C Epoxy Pad SMD T/R; Power Rating: 62.5mW; Voltage Rating: 50V; Temperature Coefficient: 100ppm/°C
R9 R12 = CMP-0001-00008-3: YAGEO - RC0402FR-07100RL. - RES, THICK FILM, 100R, 1%, 0.0625W, 0402, REEL; Power Rating: 62.5mW; Voltage Rating (DC): 50V; Value: 100; Temperature Coefficient: 100ppm/°C
R10 = CMP-0001-00006-4: Res General Purpose Thick Film 0402 100K Ohm 1% 1/16W ±100ppm/°C Molded SMD Paper T/R; Max Power Dissipation: 63mW; Working Voltage: 50V
R11 = CMP-0001-00016-1: BOURNS JW MILLER - CFG0612-FX-R010ELF - SMD Current Sense Resistor, 0.01 ohm, CFG Series, 1206 Wide, 1 W, ± 1%, Metal Foil
R13 = CMP-0001-00006-4: Res General Purpose Thick Film 0402 100K Ohm 1% 1/16W ±100ppm/°C Molded SMD Paper T/R; Voltage Rating: 50V; Power Rating: 63mW
R14 = CMP-0001-00005-6: Res Thick Film 0402 0 Ohm Molded SMD SMD Paper T/R; Tolerance: 1%; Voltage Rating: 50V; Temperature Coefficient: 200ppm/°C; Value: 0; Power Rating: 62.5mW
R15-R17 = CMP-008-0005-9: as R29 on sheet Driver
R18 = CMP-008-0005-9: as R3 on sheet battery

## Sheet pwm_to_analog.SchDoc
size A4
Used 3 times, as channels U_Driver/pta_I, U_Driver/pta_I, U_Driver/pta_I. Parts and nets are listed once, with the designators drawn on the sheet.
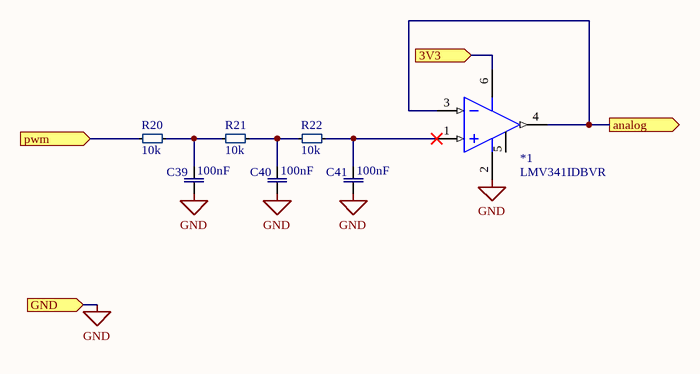
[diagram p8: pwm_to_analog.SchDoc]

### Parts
*1  LMV341IDBVR  [SOT95P280X145-6N]
C39  value 100nF  [cap0402]  (hidden comment: GRM155R71H104ME14D)
C40  value 100nF  [cap0402]  (hidden comment: GRM155R71H104ME14D)
C41  value 100nF  [cap0402]  (hidden comment: GRM155R71H104ME14D)
R20  Resistance: 10k  [SMD_0402(1005)_M]  (hidden comment: RC0402FR-0710KL)
R21  Resistance: 10k  [SMD_0402(1005)_M]  (hidden comment: RC0402FR-0710KL)
R22  Resistance: 10k  [SMD_0402(1005)_M]  (hidden comment: RC0402FR-0710KL)

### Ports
3V3 (in), analog (out), GND (in), pwm (in)

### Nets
GND: *1.2(VEE/GND) C39.1 C40.1 C41.1 ; port GND
3V3: *1.6(VCC) ; port 3V3
analog: *1.3(IN1-) *1.4(OUT1) ; port analog
pwm: R20.1 ; port pwm
Net*1_1: *1.1(IN1+) C41.2 R22.2
NetC39_2: C39.2 R20.2 R21.1
NetC40_2: C40.2 R21.2 R22.1

Not connected (* = marked no-connect by the designer): *1 5(!SHDN)

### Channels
U_Driver/pta_I: designators end in _pta_I3; ports 3V3=3V3 analog=Net*1_pta_I3_3 GND=GND pwm=NetR20_pta_I3_1
U_Driver/pta_I: designators end in _pta_I2; ports 3V3=3V3 analog=Net*1_pta_I2_3 GND=GND pwm=NetR20_pta_I2_1
U_Driver/pta_I: designators end in _pta_I1; ports 3V3=3V3 analog=Net*1_pta_I1_3 GND=GND pwm=NetR20_pta_I1_1

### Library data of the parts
*1 = CMP-ROOT-00000-1: Single Rail-To-Rail Output CMOS Operational Amplifier with Shutdown 6-SOT-23 -40 to 125; Voltage Gain: 116dB; Output Current: 32mA; Number of Channels: 1; Common Mode Rejection Ratio: 56dB; Input Offset Voltage (Vos): 250uV; Bandwidth: 1MHz; Max Supply Voltage: 5.5V; Max Frequency: 1kHz; Output Current per Channel: 113mA; Operating Supply Current: 107uA; Slew Rate: 1V/µs; Input Bias Current: 200pA; Nominal Supply Current: 170uA; Min Supply Voltage: 2.5V
C39-C41 = CMP-0001-00001-8: as C27 on sheet Booster
R20-R22 = CMP-008-0005-9: as R7 on sheet Booster

## Sheet current_sense.SchDoc
size A3
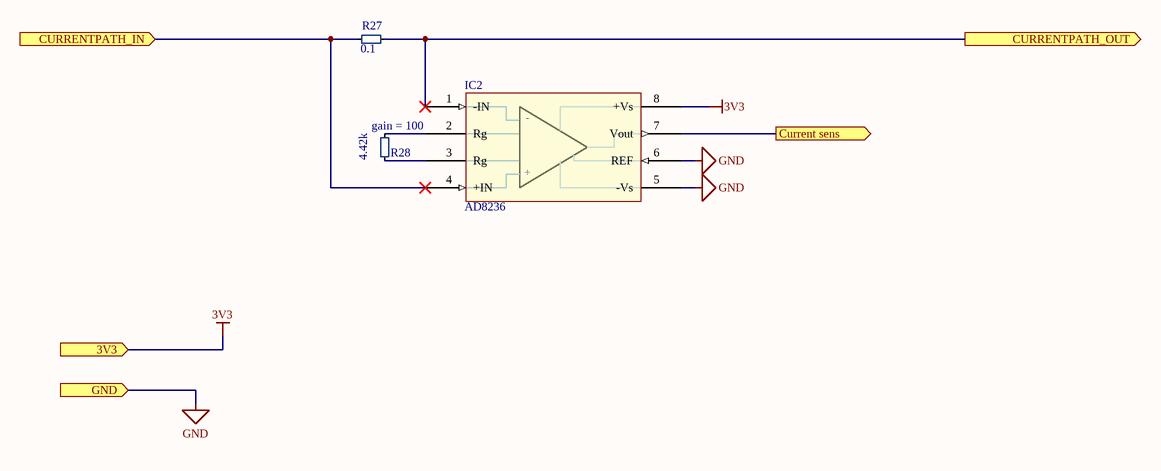
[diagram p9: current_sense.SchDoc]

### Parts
IC2  AD8236  [8-MSOP]
R27  Resistance: 0.1  [Chip2PinSM127P600-8N]  (hidden comment: ERJ-8BSFR10V)
R28  Resistance: 4.42k  [SMD_0402(1005)_M]  (hidden comment: RC0402FR-074K42L)

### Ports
3V3 (in), Current sens (out), CURRENTPATH_IN (in), CURRENTPATH_OUT (out), GND (in)

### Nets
3V3: IC2.8(+Vs) ; port 3V3
GND: IC2.5(-Vs) IC2.6(REF) ; port GND
PGND: IC2.1(-IN) R27.2 ; port CURRENTPATH_OUT
Net*2_3: IC2.7(Vout) ; port Current sens
NetCN1_2: IC2.4(+IN) R27.1 ; port CURRENTPATH_IN
NetIC2_2: IC2.2(Rg) R28.2
NetIC2_3: IC2.3(Rg) R28.1

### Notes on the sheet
- (near R28) gain = 100

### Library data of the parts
IC2 = CMP-006-0000-5: IC OPAMP INSTR 23KHZ RRO 8MSOP; Number of Channels: 1; Slew Rate: 0.011V/µs; Input Offset Voltage (Vos): 3.5mV; Common Mode Rejection Ratio: 110dB; Input Resistance: 440GR; Voltage Gain: 46.02dB; Min Supply Voltage: 1.8V; Input Bias Current: 10pA; Power Supply Rejection Ratio (PSRR): 130dB; Operating Supply Current: 40uA; Max Supply Voltage: 5.5V; Output Current per Channel: 6mA
R27 = CMP-0001-00003-2: Precision resistor, SMD 0.1 Ohm 0.33 W  ±  1 % 1206, ERJ8BSFR10V, Panasonic Automotive & Industrial Systems; Temperature Coefficient: 250ppm/°C; Value: 0.1; Tolerance: 1%; Power Rating: 330mW; Max Power Dissipation: 500mW
R28 = CMP-0001-00002-5: RES SMD 4.42K OHM 1% 1/16W 0402; Power Rating: 62.5mW; Max Power Dissipation: 63mW; Temperature Coefficient: 100ppm/°C; Voltage Rating: 50V

## Sheet linear_regulator.SchDoc
size A3
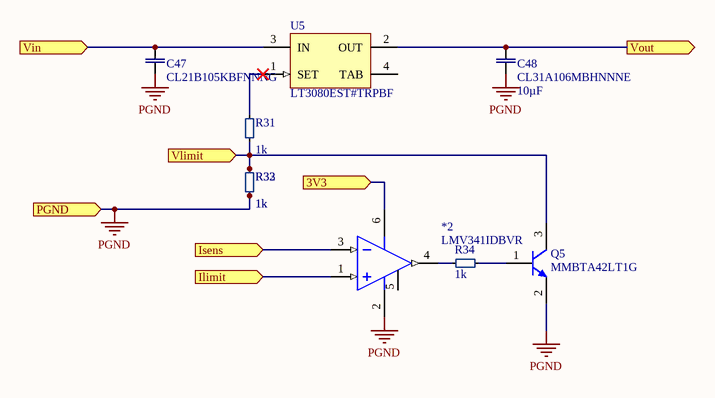
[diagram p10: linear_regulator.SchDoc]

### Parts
*2  LMV341IDBVR  [SOT95P280X145-6N]
C47  CL21B105KBFNNNG  [CAP0805]
C48  CL31A106MBHNNNE  Capacitance: 10µF  [Chip2PinSM127P600-8N]
Q5  MMBTA42LT1G  [ONSC-SOT-23-3-318-08_V]
R31  Resistance: 1k  [SMD_0402(1005)_M]  (hidden comment: RC0402FR-071KL)
R32  Resistance: 1k  [SMD_0402(1005)_M]  (hidden comment: RC0402FR-071KL)
R33  Resistance: 1k  [SMD_0402(1005)_M]  (hidden comment: RC0402FR-071KL)
R34  Resistance: 1k  [SMD_0402(1005)_M]  (hidden comment: RC0402FR-071KL)
U5  LT3080EST#TRPBF  [LT-ST-3-SOT-223_M]

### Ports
3V3 (in), Ilimit (in), Isens (in), PGND (in), Vin (in), Vlimit (in), Vout (out)

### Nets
3V3: *2.6(VCC) ; port 3V3
PGND: *2.2(VEE/GND) C47.1 C48.1 Q5.2(E) R32.1 R33.1 ; port PGND
Net*1_pta_I1_3: *2.1(IN1+) ; port Ilimit
Net*1_pta_I2_3: Q5.3(C) R31.1 R32.2 R33.2 ; port Vlimit
Net*2_3: *2.3(IN1-) ; port Isens
Net*2_4: *2.4(OUT1) R34.2
NetC18_1: C47.2 U5.3(IN) ; port Vin
NetC48_2: C48.2 U5.2(OUT) ; port Vout
NetQ5_1: Q5.1(B) R34.1
NetR31_2: R31.2 U5.1(SET)

Not connected (* = marked no-connect by the designer): *2 5(!SHDN); U5 4(TAB)

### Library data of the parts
*2 = CMP-ROOT-00000-1: as *1 on sheet pwm_to_analog
C47 = CMP-0001-00012-4: SAMSUNG ELECTRO-MECHANICS - CL21B105KBFNNNG - MLCC CAPACITORS; Voltage Rating: 50V; Dielectric: X7R; Material: Ceramic; Capacitance: 1µF; Tolerance: 10%
C48 = CMP-0001-00015-2: as C13 on sheet battery
Q5 = CMP-ROOT-00016-1: Trans GP BJT NPN 300V 0.5A Automotive 3-Pin SOT-23 T/R; Frequency: 50MHz; Emitter Base Voltage (VEBO): 6V; Number of Elements: 1; Max Collector Current: 500mA; Power Dissipation: 300mW; Max Power Dissipation: 225mW; Collector Emitter Saturation Voltage: 500mV; Element Configuration: Single; hFE Min: 25
R31-R34 = CMP-001-0000-7: as R1 on sheet battery
U5 = CMP-00005-1: IC REG LIN POS ADJ 1.1A SOT223-3; Operating Supply Current: 300uA; Quiescent Current: 500uA; Number of Regulators: 1; Output Voltage Accuracy: 1%; Min Input Voltage: 1.2V; Polarity: Positive; Dropout Voltage: 1.35V; Output Voltage: 36V

## Sheet Controll.SchDoc
size A3
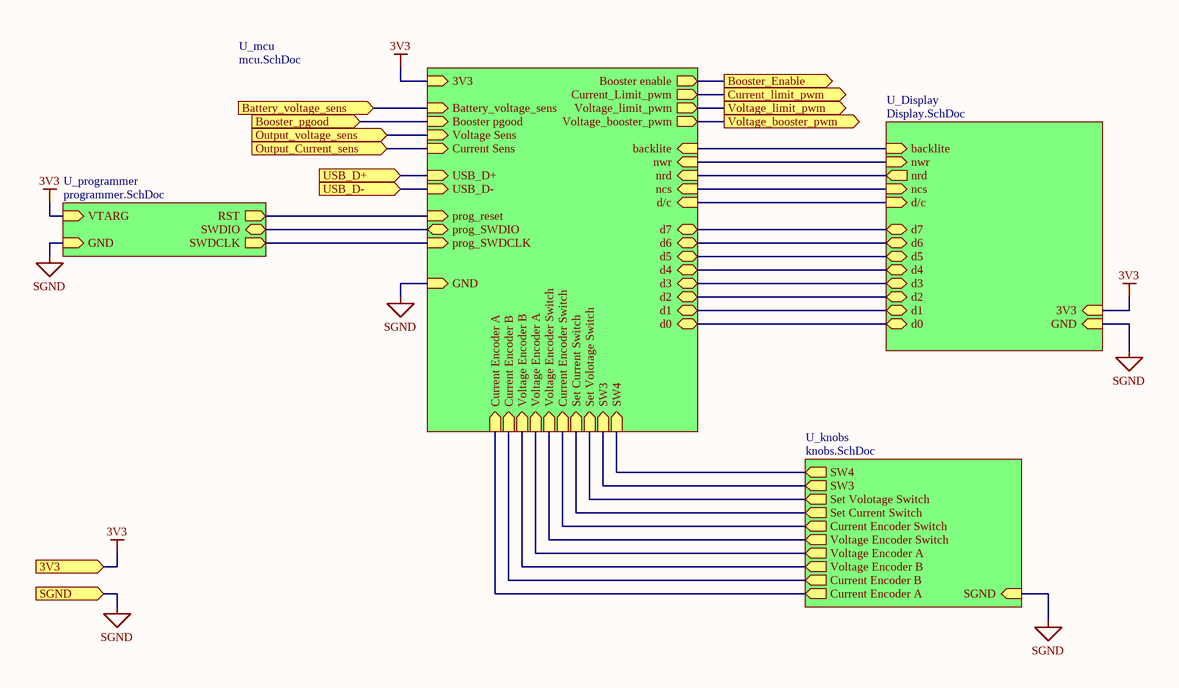
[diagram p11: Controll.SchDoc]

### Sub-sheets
U_Display = Display.SchDoc: d0 (bidir), d4 (bidir), d2 (bidir), d1 (bidir), nwr (in), d/c (in), 3V3 (in), ncs (in), d5 (bidir), d6 (bidir), GND (in), d3 (bidir), d7 (bidir), backlite (in), nrd (out)
U_knobs = knobs.SchDoc: Current Encoder A (out), Current Encoder B (out), Voltage Encoder B (out), Voltage Encoder A (out), Voltage Encoder Switch (out), Current Encoder Switch (out), Set Current Switch (out), Set Volotage Switch (out), SW3 (out), SW4 (out), SGND (in)
U_mcu = mcu.SchDoc: 3V3 (in), GND (in), Battery_voltage_sens (in), Booster enable (out), Booster pgood (in), Current_Limit_pwm (out), Voltage_limit_pwm (out), Voltage Sens (in), Current Sens (in), USB_D+ (in), USB_D- (in), nwr (in), d/c (in), ncs (in), nrd (in), backlite (in), d0 (bidir), d4 (bidir), d2 (bidir), d1 (bidir), d5 (bidir), d6 (bidir), d3 (bidir), d7 (bidir), prog_reset (in), prog_SWDIO (bidir), prog_SWDCLK (in), Voltage_booster_pwm (out), Voltage Encoder B (in), Current Encoder A (in), SW4 (in), Voltage Encoder A (in), SW3 (in), Current Encoder B (in), Current Encoder Switch (in), Set Volotage Switch (in), Voltage Encoder Switch (in), Set Current Switch (in)
U_programmer = programmer.SchDoc: VTARG (in), SWDCLK (out), GND (in), RST (out), SWDIO (bidir)

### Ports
3V3 (in), Battery_voltage_sens (in), Booster_Enable (out), Booster_pgood (in), Current_limit_pwm (out), Output_Current_sens (in), Output_voltage_sens (in), SGND (in), USB_D+ (in), USB_D- (in), Voltage_booster_pwm (out), Voltage_limit_pwm (out)

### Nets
3V3: port 3V3, sheet U_mcu/3V3, sheet U_Display/3V3, sheet U_programmer/VTARG
SGND: port SGND, sheet U_knobs/SGND, sheet U_mcu/GND, sheet U_Display/GND, sheet U_programmer/GND  [project net GND]
Net*2_3: port Output_Current_sens, sheet U_mcu/Current Sens
NetC17_1: port Battery_voltage_sens, sheet U_mcu/Battery_voltage_sens
NetCN2_1: sheet U_mcu/prog_SWDIO, sheet U_programmer/SWDIO
NetCN2_2: sheet U_mcu/prog_SWDCLK, sheet U_programmer/SWDCLK
NetCN2_3: sheet U_mcu/prog_reset, sheet U_programmer/RST
NetDisplay_23: sheet U_mcu/ncs, sheet U_Display/ncs
NetDisplay_24: sheet U_mcu/d/c, sheet U_Display/d/c
NetDisplay_25: sheet U_mcu/nwr, sheet U_Display/nwr
NetDisplay_26: sheet U_mcu/nrd, sheet U_Display/nrd
NetDisplay_28: sheet U_mcu/backlite, sheet U_Display/backlite
NetDisplay_33: sheet U_mcu/d0, sheet U_Display/d0
NetDisplay_34: sheet U_mcu/d1, sheet U_Display/d1
NetDisplay_35: sheet U_mcu/d2, sheet U_Display/d2
NetDisplay_36: sheet U_mcu/d3, sheet U_Display/d3
NetDisplay_37: sheet U_mcu/d4, sheet U_Display/d4
NetDisplay_38: sheet U_mcu/d5, sheet U_Display/d5
NetDisplay_39: sheet U_mcu/d6, sheet U_Display/d6
NetDisplay_40: sheet U_mcu/d7, sheet U_Display/d7
NetIC1_1: port Booster_Enable, sheet U_mcu/Booster enable
NetIC1_17: port Booster_pgood, sheet U_mcu/Booster pgood
NetR20_pta_I1_1: port Current_limit_pwm, sheet U_mcu/Current_Limit_pwm
NetR20_pta_I2_1: port Voltage_limit_pwm, sheet U_mcu/Voltage_limit_pwm
NetR20_pta_I3_1: port Voltage_booster_pwm, sheet U_mcu/Voltage_booster_pwm
NetR24_2: port USB_D+, sheet U_mcu/USB_D+
NetR26_2: port USB_D-, sheet U_mcu/USB_D-
NetR29_1: port Output_voltage_sens, sheet U_mcu/Voltage Sens
NetSW2_1: sheet U_knobs/Current Encoder Switch, sheet U_mcu/Current Encoder Switch
NetSW2_3: sheet U_knobs/Current Encoder B, sheet U_mcu/Current Encoder B
NetSW2_5: sheet U_knobs/Current Encoder A, sheet U_mcu/Current Encoder A
NetSW3_1: sheet U_knobs/Set Current Switch, sheet U_mcu/Set Current Switch
NetSW4_1: sheet U_knobs/Voltage Encoder Switch, sheet U_mcu/Voltage Encoder Switch
NetSW4_3: sheet U_knobs/Voltage Encoder B, sheet U_mcu/Voltage Encoder B
NetSW4_5: sheet U_knobs/Voltage Encoder A, sheet U_mcu/Voltage Encoder A
NetSW5_1: sheet U_knobs/Set Volotage Switch, sheet U_mcu/Set Volotage Switch
NetSW6_1: sheet U_knobs/SW3, sheet U_mcu/SW3
NetSW7_1: sheet U_knobs/SW4, sheet U_mcu/SW4

## Sheet knobs.SchDoc
size A3
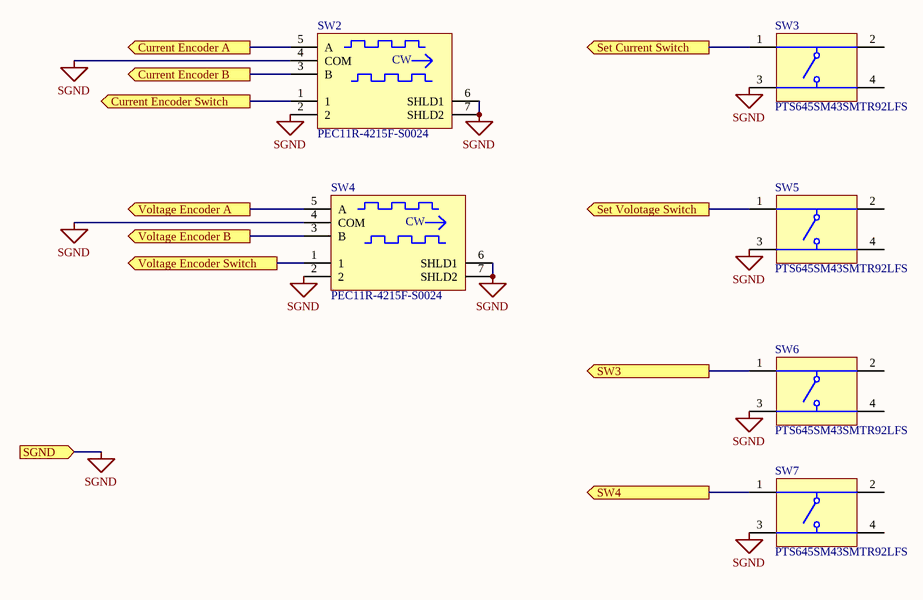
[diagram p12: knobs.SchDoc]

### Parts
SW2  PEC11R-4215F-S0024  [BOUR-PEC11R-4XXXF-SXXXX_V]
SW3  PTS645SM43SMTR92LFS  [ITT-PTS645S-4_V]
SW4  PEC11R-4215F-S0024  [BOUR-PEC11R-4XXXF-SXXXX_V]
SW5  PTS645SM43SMTR92LFS  [ITT-PTS645S-4_V]
SW6  PTS645SM43SMTR92LFS  [ITT-PTS645S-4_V]
SW7  PTS645SM43SMTR92LFS  [ITT-PTS645S-4_V]

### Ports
Current Encoder A (out), Current Encoder B (out), Current Encoder Switch (out), Set Current Switch (out), Set Volotage Switch (out), SGND (in), SW3 (out), SW4 (out), Voltage Encoder A (out), Voltage Encoder B (out), Voltage Encoder Switch (out)

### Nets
SGND: SW2.2 SW2.4(COM) SW2.6(SHLD1) SW2.7(SHLD2) SW3.3 SW4.2 SW4.4(COM) SW4.6(SHLD1) SW4.7(SHLD2) SW5.3 SW6.3 SW7.3 ; port SGND  [project net GND]
NetSW2_1: SW2.1 ; port Current Encoder Switch
NetSW2_3: SW2.3(B) ; port Current Encoder B
NetSW2_5: SW2.5(A) ; port Current Encoder A
NetSW3_1: SW3.1 ; port Set Current Switch
NetSW4_1: SW4.1 ; port Voltage Encoder Switch
NetSW4_3: SW4.3(B) ; port Voltage Encoder B
NetSW4_5: SW4.5(A) ; port Voltage Encoder A
NetSW5_1: SW5.1 ; port Set Volotage Switch
NetSW6_1: SW6.1 ; port SW3
NetSW7_1: SW7.1 ; port SW4

Not connected (* = marked no-connect by the designer): SW3 2 4; SW5 2 4; SW6 2 4; SW7 2 4

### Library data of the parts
SW2 SW4 = CMP-ROOT-00012-1: BOURNS - PEC11R-4215F-S0024 - Rotary Encoder, Mechanical, Incremental, 24 PPR, 24 Detents, Vertical, With Momentary Push Switch; Hole Diameter: 1.8mm; Detent: Yes; Pulses per Revolution: 24; Output Type: Quadrature,Incremental; Number of Channels: 2
SW3 SW5-SW7 = CMP-ROOT-00013-1: SWITCH TACTILE SPST-NO 0.05A 12V; Actuator Material: Nylon,Polyamide; Switch Function: Off-Mom; Throw Configuration: SPST; Contact Resistance: 100mR; Mechanical Life: 100000Cycles; Actuator Length: 0.85mm; Illumination Type: Non-Illuminated,Illuminated; Max Current Rating: 50mA; Operating Force: 160gf; Actuator Type: Standard

## Sheet mcu.SchDoc
size A3
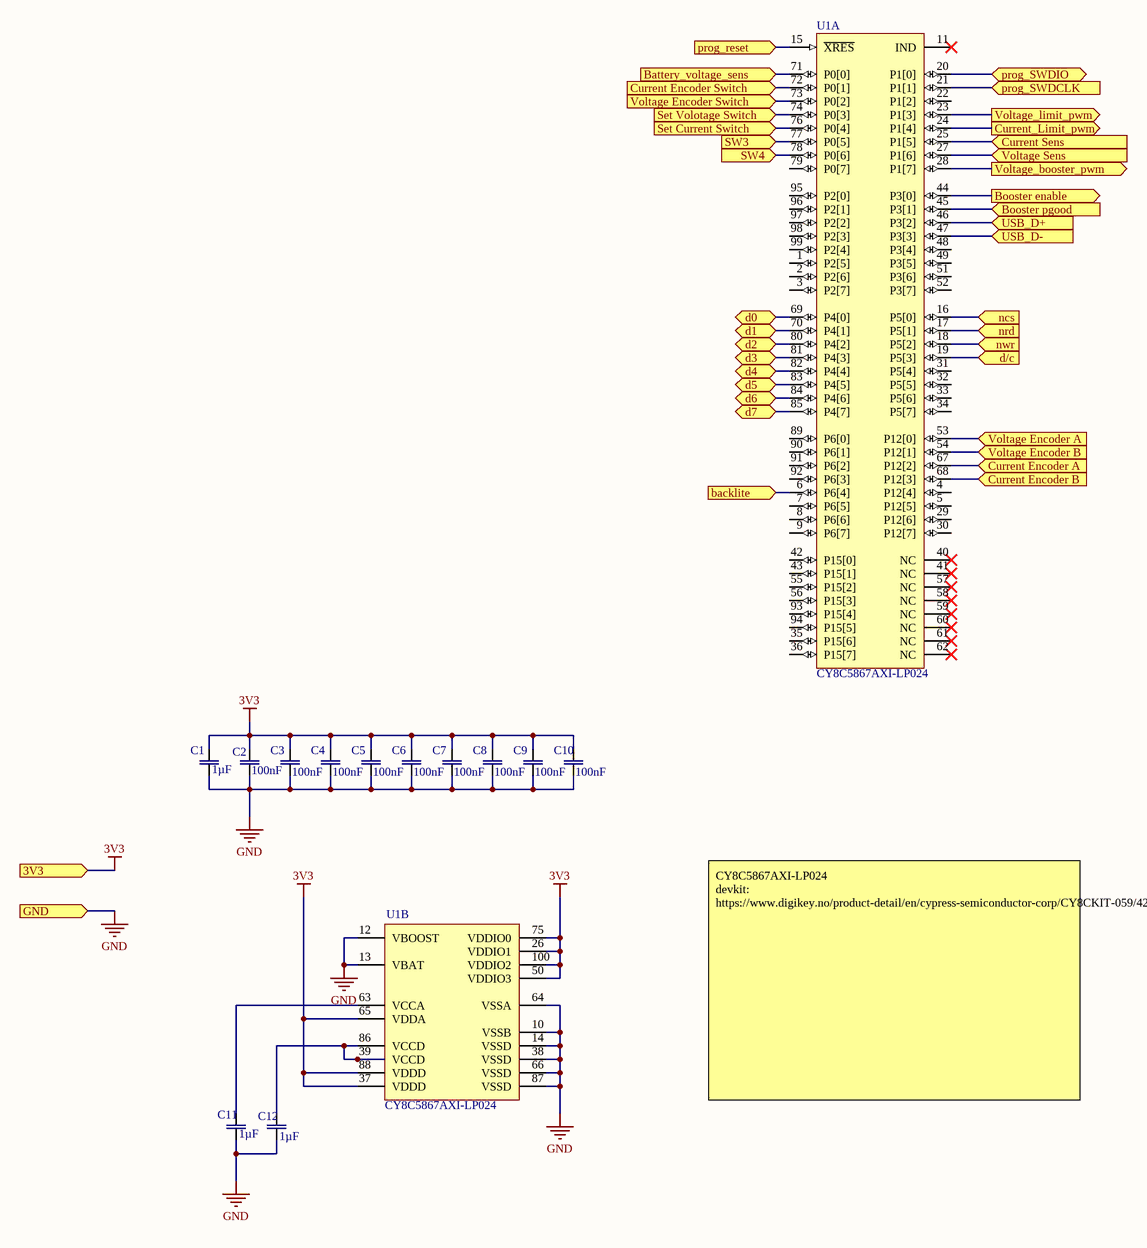
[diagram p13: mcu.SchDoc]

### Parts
C1  Capacitance: 1µF  [CAP0805]  (hidden comment: CL21B105KBFNNNG)
C2  Capacitance: 100nF  [cap0402]  (hidden comment: GRM155R71H104ME14D)
C3  Capacitance: 100nF  [cap0402]  (hidden comment: GRM155R71H104ME14D)
C4  Capacitance: 100nF  [cap0402]  (hidden comment: GRM155R71H104ME14D)
C5  Capacitance: 100nF  [cap0402]  (hidden comment: GRM155R71H104ME14D)
C6  Capacitance: 100nF  [cap0402]  (hidden comment: GRM155R71H104ME14D)
C7  Capacitance: 100nF  [cap0402]  (hidden comment: GRM155R71H104ME14D)
C8  Capacitance: 100nF  [cap0402]  (hidden comment: GRM155R71H104ME14D)
C9  Capacitance: 100nF  [cap0402]  (hidden comment: GRM155R71H104ME14D)
C10  Capacitance: 100nF  [cap0402]  (hidden comment: GRM155R71H104ME14D)
C11  Capacitance: 1µF  [CAP0805]  (hidden comment: CL21B105KBFNNNG)
C12  Capacitance: 1µF  [CAP0805]  (hidden comment: CL21B105KBFNNNG)
U1  CY8C5867AXI-LP024  [CYP-AX100_M]  (parts A,B of 2)

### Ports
3V3 (in), backlite (in), Battery_voltage_sens (in), Booster enable (out), Booster pgood (in), Current Encoder A (in), Current Encoder B (in), Current Encoder Switch (in), Current Sens (in), Current_Limit_pwm (out), d0 (bidir), d1 (bidir), d2 (bidir), d3 (bidir), d4 (bidir), d5 (bidir), d6 (bidir), d7 (bidir), d/c (in), GND (in), ncs (in), nrd (in), nwr (in), prog_reset (in), prog_SWDCLK (in), prog_SWDIO (bidir), Set Current Switch (in), Set Volotage Switch (in), SW3 (in), SW4 (in), USB_D+ (in), USB_D- (in), Voltage Encoder A (in), Voltage Encoder B (in), Voltage Encoder Switch (in), Voltage Sens (in), Voltage_booster_pwm (out), Voltage_limit_pwm (out)

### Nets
3V3: C1.2 C2.2 C3.2 C4.2 C5.2 C6.2 C7.2 C8.2 C9.2 C10.2 U1.26(VDDIO1) U1.37(VDDD) U1.50(VDDIO3) U1.65(VDDA) U1.75(VDDIO0) U1.88(VDDD) U1.100(VDDIO2) ; port 3V3
GND: C1.1 C2.1 C3.1 C4.1 C5.1 C6.1 C7.1 C8.1 C9.1 C10.1 C11.1 C12.1 U1.10(VSSB) U1.12(VBOOST) U1.13(VBAT) U1.14(VSSD) U1.38(VSSD) U1.64(VSSA) U1.66(VSSD) U1.87(VSSD) ; port GND
Net*2_3: U1.25(P1[5]) ; port Current Sens
NetC11_2: C11.2 U1.63(VCCA)
NetC12_2: C12.2 U1.39(VCCD) U1.86(VCCD)
NetC17_1: U1.71(P0[0]) ; port Battery_voltage_sens
NetCN2_1: U1.20(P1[0]) ; port prog_SWDIO
NetCN2_2: U1.21(P1[1]) ; port prog_SWDCLK
NetCN2_3: U1.15(~{XRES}) ; port prog_reset
NetDisplay_23: U1.16(P5[0]) ; port ncs
NetDisplay_24: U1.19(P5[3]) ; port d/c
NetDisplay_25: U1.18(P5[2]) ; port nwr
NetDisplay_26: U1.17(P5[1]) ; port nrd
NetDisplay_28: U1.6(P6[4]) ; port backlite
NetDisplay_33: U1.69(P4[0]) ; port d0
NetDisplay_34: U1.70(P4[1]) ; port d1
NetDisplay_35: U1.80(P4[2]) ; port d2
NetDisplay_36: U1.81(P4[3]) ; port d3
NetDisplay_37: U1.82(P4[4]) ; port d4
NetDisplay_38: U1.83(P4[5]) ; port d5
NetDisplay_39: U1.84(P4[6]) ; port d6
NetDisplay_40: U1.85(P4[7]) ; port d7
NetIC1_1: U1.44(P3[0]) ; port Booster enable
NetIC1_17: U1.45(P3[1]) ; port Booster pgood
NetR20_pta_I1_1: U1.24(P1[4]) ; port Current_Limit_pwm
NetR20_pta_I2_1: U1.23(P1[3]) ; port Voltage_limit_pwm
NetR20_pta_I3_1: U1.28(P1[7]) ; port Voltage_booster_pwm
NetR24_2: U1.46(P3[2]) ; port USB_D+
NetR26_2: U1.47(P3[3]) ; port USB_D-
NetR29_1: U1.27(P1[6]) ; port Voltage Sens
NetSW2_1: U1.72(P0[1]) ; port Current Encoder Switch
NetSW2_3: U1.68(P12[3]) ; port Current Encoder B
NetSW2_5: U1.67(P12[2]) ; port Current Encoder A
NetSW3_1: U1.76(P0[4]) ; port Set Current Switch
NetSW4_1: U1.73(P0[2]) ; port Voltage Encoder Switch
NetSW4_3: U1.54(P12[1]) ; port Voltage Encoder B
NetSW4_5: U1.53(P12[0]) ; port Voltage Encoder A
NetSW5_1: U1.74(P0[3]) ; port Set Volotage Switch
NetSW6_1: U1.77(P0[5]) ; port SW3
NetSW7_1: U1.78(P0[6]) ; port SW4

Not connected (* = marked no-connect by the designer): U1 1(P2[5]) 2(P2[6]) 3(P2[7]) 4(P12[4]) 5(P12[5]) 7(P6[5]) 8(P6[6]) 9(P6[7]) 11(IND)* 22(P1[2]) 29(P12[6]) 30(P12[7]) 31(P5[4]) 32(P5[5]) 33(P5[6]) 34(P5[7]) 35(P15[6]) 36(P15[7]) 40(NC)* 41(NC)* 42(P15[0]) 43(P15[1]) 48(P3[4]) 49(P3[5]) 51(P3[6]) 52(P3[7]) 55(P15[2]) 56(P15[3]) 57(NC)* 58(NC)* 59(NC)* 60(NC)* 61(NC)* 62(NC)* 79(P0[7]) 89(P6[0]) 90(P6[1]) 91(P6[2]) 92(P6[3]) 93(P15[4]) 94(P15[5]) 95(P2[0]) 96(P2[1]) 97(P2[2]) 98(P2[3]) 99(P2[4])

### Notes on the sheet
- CY8C5867AXI-LP024
  devkit: https://www.digikey.no/product-detail/en/cypress-semiconductor-corp/CY8CKIT-059/428-3390-ND/5184557

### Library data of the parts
C1 C11 C12 = CMP-0001-00012-4: as C37 on sheet LDO
C2-C10 = CMP-0001-00001-8: as C14 on sheet battery
U1 = CMP-00001-4: IC MCU 32BIT 128KB FLASH 100TQFP; Min Supply Voltage: 1.71V; RAM Size: 32KB; Max Frequency: 67MHz; Data Bus Width: 32b; Peripherals: POR,PWM,WDT,DMA,LCD,CapSense; Number of I/Os: 62; Core Architecture: ARM; Interface: I2C,SPI,UART,USB,USART,LIN; Oscillator Type: Internal; Number of Timers/Counters: 4; Max Supply Voltage: 5.5V; Number of ADC Channels: 2

## Sheet Display.SchDoc
size A3
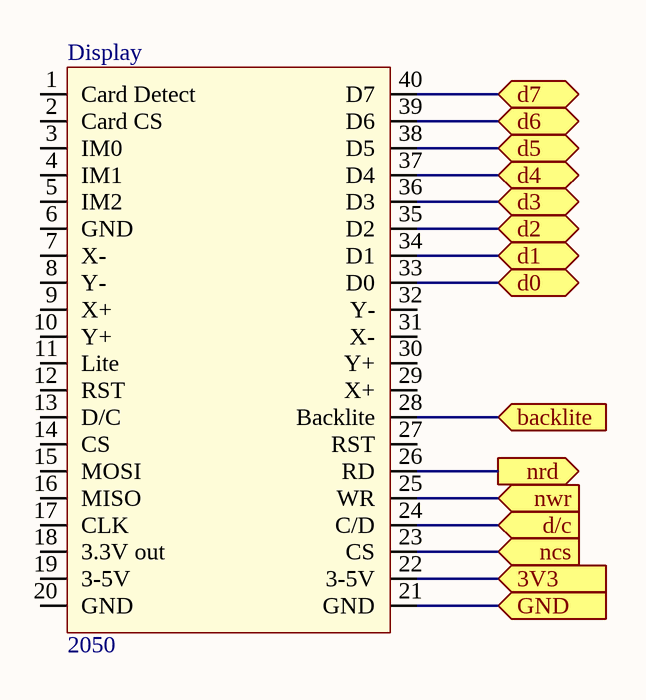
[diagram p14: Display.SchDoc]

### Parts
Display  2050  [2050-Footprint-1]

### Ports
3V3 (in), backlite (in), d0 (bidir), d1 (bidir), d2 (bidir), d3 (bidir), d4 (bidir), d5 (bidir), d6 (bidir), d7 (bidir), d/c (in), GND (in), ncs (in), nrd (out), nwr (in)

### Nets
3V3: Display.22(3-5V) ; port 3V3
GND: Display.21(GND) ; port GND
NetDisplay_23: Display.23(CS) ; port ncs
NetDisplay_24: Display.24(C/D) ; port d/c
NetDisplay_25: Display.25(WR) ; port nwr
NetDisplay_26: Display.26(RD) ; port nrd
NetDisplay_28: Display.28(Backlite) ; port backlite
NetDisplay_33: Display.33(D0) ; port d0
NetDisplay_34: Display.34(D1) ; port d1
NetDisplay_35: Display.35(D2) ; port d2
NetDisplay_36: Display.36(D3) ; port d3
NetDisplay_37: Display.37(D4) ; port d4
NetDisplay_38: Display.38(D5) ; port d5
NetDisplay_39: Display.39(D6) ; port d6
NetDisplay_40: Display.40(D7) ; port d7

Not connected (* = marked no-connect by the designer): Display 1(Card_Detect) 2(Card_CS) 3(IM0) 4(IM1) 5(IM2) 6(GND) 7(X-) 8(Y-) 9(X+) 10(Y+) 11(Lite) 12(RST) 13(D/C) 14(CS) 15(MOSI) 16(MISO) 17(CLK) 18(3.3V_out) 19(3-5V) 20(GND) 27(RST) 29(X+) 30(Y+) 31(X-) 32(Y-)

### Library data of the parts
Display = CMP-ROOT-00015-3: 3.5" TFT 320X480 TOUCHSCREEN; Backlight Type: LED; Diagonal Size: 3.5inch; Touchscreen: Resistive; Resolution (height): 480pixel; Resolution (width): 320pixel; Interface: Serial,Parallel

## Sheet programmer.SchDoc
size A3
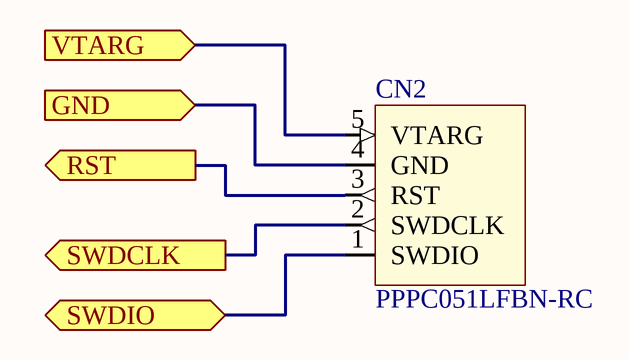
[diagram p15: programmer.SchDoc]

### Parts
CN2  PPPC051LFBN-RC  [PR20203VBNN-Footprint-1]

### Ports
GND (in), RST (out), SWDCLK (out), SWDIO (bidir), VTARG (in)

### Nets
3V3: CN2.5(VTARG) ; port VTARG
GND: CN2.4(GND) ; port GND
NetCN2_1: CN2.1(SWDIO) ; port SWDIO
NetCN2_2: CN2.2(SWDCLK) ; port SWDCLK
NetCN2_3: CN2.3(RST) ; port RST

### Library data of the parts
CN2 = CMP-ROOT-00017-8: CONN HDR 5POS 0.1 GOLD PCB; Pitch: 0.1inch; System: Connector; Connector Type: Header,Socket; Number of Positions: 5

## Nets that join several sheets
3V3: LDO (C38.2 U3.5), U_Driver/pta_I (*1_pta_I3.6), current_sense (IC2.8), linear_regulator (*2.6), U_Driver/pta_I (*1_pta_I2.6), U_Driver/pta_I (*1_pta_I1.6), mcu (17 pins), Display (Display.22), programmer (CN2.5)
GND: LDO (C37.1 C38.1 R19.2 U3.2), Driver (R30.1), Booster (13 pins), U_Driver/pta_I (*1_pta_I3.2 C39_pta_I3.1 C40_pta_I3.1 C41_pta_I3.1), current_sense (IC2.5 IC2.6), U_Driver/pta_I (*1_pta_I2.2 C39_pta_I2.1 C40_pta_I2.1 C41_pta_I2.1), U_Driver/pta_I (*1_pta_I1.2 C39_pta_I1.1 C40_pta_I1.1 C41_pta_I1.1), knobs (12 pins), mcu (20 pins), Display (Display.21), programmer (CN2.4)
PGND: LDO (R19.1), battery (8 pins), usb_isolator (C45.1 ISO1.4 U4.16), Booster (15 pins), current_sense (IC2.1 R27.2), linear_regulator (6 pins)
Net*1_pta_I1_3: linear_regulator (*2.1), U_Driver/pta_I (*1_pta_I1.3 *1_pta_I1.4)
Net*1_pta_I2_3: linear_regulator (Q5.3 R31.1 R32.2 R33.2), U_Driver/pta_I (*1_pta_I2.3 *1_pta_I2.4)
Net*1_pta_I3_3: Booster (R16.2), U_Driver/pta_I (*1_pta_I3.3 *1_pta_I3.4)
Net*2_3: current_sense (IC2.7), linear_regulator (*2.3), mcu (U1.25)
NetC13_2: battery (C13.2 C14.2 R1.2 U2.4), usb_isolator (5 pins)
NetC17_1: LDO (C37.2 U3.1 U3.3), battery (R3.1 R3.2 R4.2 SW1.3), Booster (8 pins), mcu (U1.71)
NetC18_1: Driver (R29.2), Booster (8 pins), linear_regulator (C47.2 U5.3)
NetC42_1: usb (13 pins), usb_isolator (6 pins)
NetC42_2: usb (J1.A4-B9 J1.B4-A9 J2.1), usb_isolator (C42.2 C43.2 ISO1.1 U4.1)
NetC48_2: Driver (CN1.1), linear_regulator (C48.2 U5.2)
NetCN1_2: Driver (CN1.2), current_sense (IC2.4 R27.1)
NetCN2_1: mcu (U1.20), programmer (CN2.1)
NetCN2_2: mcu (U1.21), programmer (CN2.2)
NetCN2_3: mcu (U1.15), programmer (CN2.3)
NetDisplay_23: mcu (U1.16), Display (Display.23)
NetDisplay_24: mcu (U1.19), Display (Display.24)
NetDisplay_25: mcu (U1.18), Display (Display.25)
NetDisplay_26: mcu (U1.17), Display (Display.26)
NetDisplay_28: mcu (U1.6), Display (Display.28)
NetDisplay_33: mcu (U1.69), Display (Display.33)
NetDisplay_34: mcu (U1.70), Display (Display.34)
NetDisplay_35: mcu (U1.80), Display (Display.35)
NetDisplay_36: mcu (U1.81), Display (Display.36)
NetDisplay_37: mcu (U1.82), Display (Display.37)
NetDisplay_38: mcu (U1.83), Display (Display.38)
NetDisplay_39: mcu (U1.84), Display (Display.39)
NetDisplay_40: mcu (U1.85), Display (Display.40)
NetIC1_1: Booster (IC1.1 R7.2), mcu (U1.44)
NetIC1_17: Booster (IC1.17 R7.1), mcu (U1.45)
NetJ1_A6: usb (J1.A6 J1.B6 J2.3), usb_isolator (R23.1)
NetJ1_A7: usb (J1.A7 J1.B7 J2.2), usb_isolator (R25.1)
NetR20_pta_I1_1: U_Driver/pta_I (R20_pta_I1.1), mcu (U1.24)
NetR20_pta_I2_1: U_Driver/pta_I (R20_pta_I2.1), mcu (U1.23)
NetR20_pta_I3_1: U_Driver/pta_I (R20_pta_I3.1), mcu (U1.28)
NetR24_2: usb_isolator (R24.2), mcu (U1.46)
NetR26_2: usb_isolator (R26.2), mcu (U1.47)
NetR29_1: Driver (R29.1 R30.2), mcu (U1.27)
NetSW2_1: knobs (SW2.1), mcu (U1.72)
NetSW2_3: knobs (SW2.3), mcu (U1.68)
NetSW2_5: knobs (SW2.5), mcu (U1.67)
NetSW3_1: knobs (SW3.1), mcu (U1.76)
NetSW4_1: knobs (SW4.1), mcu (U1.73)
NetSW4_3: knobs (SW4.3), mcu (U1.54)
NetSW4_5: knobs (SW4.5), mcu (U1.53)
NetSW5_1: knobs (SW5.1), mcu (U1.74)
NetSW6_1: knobs (SW6.1), mcu (U1.77)
NetSW7_1: knobs (SW7.1), mcu (U1.78)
